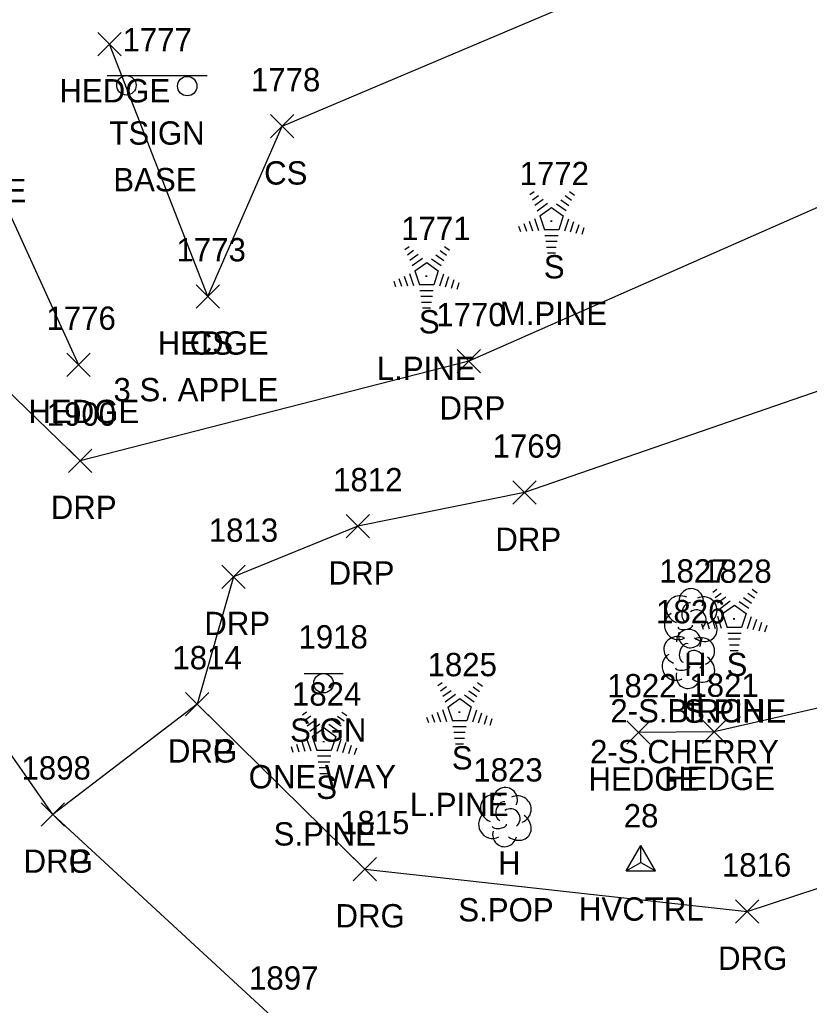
# Model space of a CAD drawing. Extents: x 1477930 to 1480780, y 774090 to 784647.
# Drawn here: x 1478985.1 to 1479052.8, y 774378.4 to 774462.9 of the extents above; entities that cross this region are included whole.
import ezdxf

# ---------------------------------------------------------------- set-up
doc = ezdxf.new("R2010")
doc.units = 0
for name, color, linetype in [('C_A', 7, 'Continuous'), ('C_I', 7, 'Continuous'), ('CPSM', 7, 'Continuous'), ('L_A', 7, 'Continuous'), ('L_C', 7, 'Continuous'), ('L_I', 7, 'Continuous'), ('L_TIC', 7, 'Continuous'), ('LAHR', 7, 'Continuous'), ('LELB', 7, 'Continuous'), ('LTC', 7, 'Continuous'), ('LTD', 7, 'Continuous'), ('R_A', 7, 'Continuous'), ('R_I', 7, 'Continuous'), ('R_TIC', 7, 'Continuous'), ('RDG', 7, 'Continuous'), ('RDP', 7, 'Continuous'), ('S_A', 7, 'Continuous'), ('S_C', 7, 'Continuous'), ('S_I', 7, 'Continuous'), ('SSGN', 7, 'Continuous')]:
    doc.layers.add(name, color=color, linetype=linetype)

msp = doc.modelspace()

# ---------------------------------------------------------------- linework, layer by layer
at = {"layer": 'CPSM'}
for p, q in [((1479037.081, 774389.906), (1479038.331, 774392.071)), ((1479039.581, 774389.906), (1479038.331, 774392.071)), ((1479038.332, 774390.627), (1479038.331, 774392.071)), ((1479037.081, 774389.906), (1479038.332, 774390.627)), ((1479038.332, 774390.627), (1479038.332, 774390.627)), ((1479038.332, 774390.627), (1479039.581, 774389.906)), ((1479037.081, 774389.906), (1479039.581, 774389.906))]:
    msp.add_line(p, q, dxfattribs=at)
at = {"layer": 'L_TIC'}
for points in [[(1478991.765, 774459.811), (1478993.765, 774461.811)], [(1478993.765, 774459.811), (1478991.765, 774461.811)], [(1479006.585, 774452.764), (1479008.585, 774454.764)], [(1479008.585, 774452.764), (1479006.585, 774454.764)], [(1479000.201, 774438.175), (1479002.201, 774440.175)], [(1479002.201, 774438.175), (1479000.201, 774440.175)], [(1479000.201, 774438.175), (1479002.201, 774440.175)], [(1479002.201, 774438.175), (1479000.201, 774440.175)], [(1478989.107, 774432.304), (1478991.107, 774434.304)], [(1478991.107, 774432.304), (1478989.107, 774434.304)], [(1479037.139, 774400.78), (1479039.139, 774402.78)], [(1479039.139, 774400.78), (1479037.139, 774402.78)], [(1479043.623, 774400.826), (1479045.623, 774402.826)], [(1479045.623, 774400.826), (1479043.623, 774402.826)]]:
    msp.add_lwpolyline(points, dxfattribs=at)
at = {"layer": 'LAHR'}
for points in [[(1479001.201, 774439.175), (1478992.765, 774460.811)], [(1478979.611, 774456.25), (1478990.107, 774433.304)], [(1479070.273, 774407.681), (1479044.623, 774401.826), (1479038.139, 774401.78)]]:
    msp.add_lwpolyline(points, dxfattribs=at)
at = {"layer": 'LELB'}
msp.add_lwpolyline([(1479001.201, 774439.175), (1479007.585, 774453.764), (1479050.28, 774471.874), (1479091.551, 774493.14), (1479101.547, 774520.781)], dxfattribs=at)
at = {"layer": 'LTC'}
for p, q in [((1479028.82, 774447.922), (1479029.175, 774448.18)), ((1479032.218, 774448.163), (1479032.638, 774447.858)), ((1479029.03, 774447.457), (1479029.559, 774447.841)), ((1479029.239, 774446.991), (1479029.943, 774447.502)), ((1479031.476, 774447.466), (1479032.155, 774446.972)), ((1479031.847, 774447.814), (1479032.397, 774447.415)), ((1479029.449, 774446.525), (1479030.327, 774447.163)), ((1479029.673, 774446.07), (1479030.685, 774446.805)), ((1479030.685, 774446.805), (1479031.682, 774446.08)), ((1479031.105, 774447.118), (1479031.915, 774446.529)), ((1479028.763, 774445.635), (1479029.035, 774444.799)), ((1479029.219, 774445.851), (1479029.55, 774444.832)), ((1479029.673, 774446.07), (1479030.06, 774444.877)), ((1479031.682, 774446.08), (1479031.291, 774444.877)), ((1479032.12, 774445.809), (1479031.782, 774444.769)), ((1479032.564, 774445.559), (1479032.277, 774444.674)), ((1479027.853, 774445.202), (1479028.005, 774444.734)), ((1479028.308, 774445.418), (1479028.52, 774444.767)), ((1479031.291, 774444.877), (1479030.06, 774444.877)), ((1479033.009, 774445.309), (1479032.772, 774444.579)), ((1479033.453, 774445.058), (1479033.266, 774444.484)), ((1479031.253, 774444.377), (1479030.108, 774444.377)), ((1479031.169, 774443.877), (1479030.18, 774443.877)), ((1479018.103, 774443.206), (1479018.457, 774443.464)), ((1479018.312, 774442.741), (1479018.842, 774443.125)), ((1479021.13, 774443.098), (1479021.68, 774442.699)), ((1479021.501, 774443.447), (1479021.92, 774443.142)), ((1479031.085, 774443.377), (1479030.253, 774443.377)), ((1479018.522, 774442.275), (1479019.226, 774442.786)), ((1479018.732, 774441.809), (1479019.61, 774442.447)), ((1479020.388, 774442.402), (1479021.197, 774441.813)), ((1479020.759, 774442.75), (1479021.438, 774442.256)), ((1479031.001, 774442.877), (1479030.326, 774442.877)), ((1479018.956, 774441.354), (1479019.968, 774442.089)), ((1479018.956, 774441.354), (1479019.343, 774440.161)), ((1479019.968, 774442.089), (1479020.965, 774441.364)), ((1479020.965, 774441.364), (1479020.574, 774440.161)), ((1479017.135, 774440.485), (1479017.287, 774440.017)), ((1479017.591, 774440.702), (1479017.802, 774440.05)), ((1479018.046, 774440.919), (1479018.317, 774440.083)), ((1479018.502, 774441.135), (1479018.832, 774440.116)), ((1479021.402, 774441.093), (1479021.065, 774440.053)), ((1479021.847, 774440.842), (1479021.56, 774439.958)), ((1479022.292, 774440.592), (1479022.055, 774439.863)), ((1479020.574, 774440.161), (1479019.343, 774440.161)), ((1479020.535, 774439.661), (1479019.391, 774439.661)), ((1479022.736, 774440.342), (1479022.549, 774439.768)), ((1479020.452, 774439.161), (1479019.463, 774439.161)), ((1479020.368, 774438.661), (1479019.536, 774438.661)), ((1479020.284, 774438.161), (1479019.609, 774438.161)), ((1479044.495, 774413.813), (1479044.85, 774414.07)), ((1479044.705, 774413.348), (1479045.234, 774413.732)), ((1479047.522, 774413.705), (1479048.072, 774413.306)), ((1479047.893, 774414.053), (1479048.312, 774413.749)), ((1479044.914, 774412.882), (1479045.618, 774413.393)), ((1479045.124, 774412.416), (1479046.002, 774413.054)), ((1479045.348, 774411.961), (1479046.36, 774412.695)), ((1479046.36, 774412.695), (1479047.357, 774411.97)), ((1479046.78, 774413.008), (1479047.59, 774412.42)), ((1479047.151, 774413.357), (1479047.83, 774412.863)), ((1479044.894, 774411.742), (1479045.225, 774410.723)), ((1479045.348, 774411.961), (1479045.735, 774410.768)), ((1479047.357, 774411.97), (1479046.966, 774410.768)), ((1479043.527, 774411.092), (1479043.68, 774410.624)), ((1479043.983, 774411.309), (1479044.195, 774410.657)), ((1479044.438, 774411.525), (1479044.71, 774410.69)), ((1479047.795, 774411.7), (1479047.457, 774410.66)), ((1479048.239, 774411.449), (1479047.952, 774410.565)), ((1479048.684, 774411.199), (1479048.447, 774410.47)), ((1479049.128, 774410.949), (1479048.941, 774410.375)), ((1479046.966, 774410.768), (1479045.735, 774410.768)), ((1479046.927, 774410.268), (1479045.783, 774410.268)), ((1479046.844, 774409.768), (1479045.855, 774409.768)), ((1479046.76, 774409.268), (1479045.928, 774409.268)), ((1479046.676, 774408.768), (1479046.001, 774408.768)), ((1479020.931, 774405.802), (1479021.286, 774406.059)), ((1479024.329, 774406.042), (1479024.749, 774405.738)), ((1479021.141, 774405.337), (1479021.67, 774405.721)), ((1479021.35, 774404.871), (1479022.054, 774405.382)), ((1479021.56, 774404.405), (1479022.438, 774405.043)), ((1479023.216, 774404.997), (1479024.026, 774404.409)), ((1479023.587, 774405.346), (1479024.266, 774404.852)), ((1479023.958, 774405.694), (1479024.508, 774405.295)), ((1479021.784, 774403.95), (1479022.796, 774404.684)), ((1479022.796, 774404.684), (1479023.793, 774403.959)), ((1479009.302, 774403.279), (1479009.656, 774403.537)), ((1479012.7, 774403.52), (1479013.119, 774403.215)), ((1479020.419, 774403.298), (1479020.631, 774402.646)), ((1479020.874, 774403.514), (1479021.146, 774402.679)), ((1479021.33, 774403.731), (1479021.661, 774402.712)), ((1479021.784, 774403.95), (1479022.171, 774402.757)), ((1479023.793, 774403.959), (1479023.402, 774402.757)), ((1479024.231, 774403.689), (1479023.893, 774402.649)), ((1479024.675, 774403.438), (1479024.388, 774402.554)), ((1479009.511, 774402.814), (1479010.041, 774403.198)), ((1479009.721, 774402.348), (1479010.425, 774402.859)), ((1479009.931, 774401.882), (1479010.809, 774402.52)), ((1479011.587, 774402.475), (1479012.396, 774401.886)), ((1479011.958, 774402.823), (1479012.637, 774402.329)), ((1479012.329, 774403.171), (1479012.878, 774402.772)), ((1479019.964, 774403.081), (1479020.116, 774402.613)), ((1479023.402, 774402.757), (1479022.171, 774402.757)), ((1479025.12, 774403.188), (1479024.883, 774402.459)), ((1479025.564, 774402.938), (1479025.377, 774402.364)), ((1479010.155, 774401.427), (1479011.167, 774402.162)), ((1479011.167, 774402.162), (1479012.164, 774401.437)), ((1479023.364, 774402.257), (1479022.219, 774402.257)), ((1479023.28, 774401.757), (1479022.291, 774401.757)), ((1479008.79, 774400.775), (1479009.001, 774400.123)), ((1479009.245, 774400.992), (1479009.516, 774400.156)), ((1479009.701, 774401.208), (1479010.031, 774400.189)), ((1479010.155, 774401.427), (1479010.542, 774400.234)), ((1479012.164, 774401.437), (1479011.773, 774400.234)), ((1479012.601, 774401.166), (1479012.263, 774400.126)), ((1479013.046, 774400.915), (1479012.758, 774400.031)), ((1479023.196, 774401.257), (1479022.364, 774401.257)), ((1479023.112, 774400.757), (1479022.437, 774400.757)), ((1479008.334, 774400.558), (1479008.486, 774400.09)), ((1479011.773, 774400.234), (1479010.542, 774400.234)), ((1479013.491, 774400.665), (1479013.253, 774399.936)), ((1479013.935, 774400.415), (1479013.748, 774399.841)), ((1479011.734, 774399.734), (1479010.59, 774399.734)), ((1479011.651, 774399.234), (1479010.662, 774399.234)), ((1479011.567, 774398.734), (1479010.735, 774398.734)), ((1479011.483, 774398.234), (1479010.808, 774398.234))]:
    msp.add_line(p, q, dxfattribs=at)
at = {"layer": 'LTD'}
for p, q in [((1479042.603, 774411.627), (1479042.603, 774411.627)), ((1479042.603, 774411.627), (1479042.603, 774411.627)), ((1479042.39, 774408.133), (1479042.39, 774408.133)), ((1479042.39, 774408.133), (1479042.39, 774408.133)), ((1479026.657, 774394.562), (1479026.657, 774394.562)), ((1479026.657, 774394.562), (1479026.657, 774394.562))]:
    msp.add_line(p, q, dxfattribs=at)
for centre in [(1479042.65, 774413.061), (1479042.436, 774409.567), (1479026.704, 774395.996)]:
    msp.add_arc(centre, 1.047, 335.52715, 180.95627, dxfattribs=at)
for centre, major_axis, ratio, start_param, end_param in [((1479041.811, 774412.294), (1.21, -0.512), 0.895232, 1.570796, 4.712389), ((1479043.644, 774412.211), (-1.141, -0.483), 0.949671, 1.570796, 4.712389), ((1479042.394, 774412.086), (-0.208, -0.792), 0.645439, 3.141593, 6.283185), ((1479041.52, 774410.919), (0.584, -1.042), 0.959034, 3.141593, 6.283185), ((1479043.103, 774411.461), (-0.5, 0.667), 0.989748, 3.141593, 6.283185), ((1479042.145, 774410.877), (-0.625, -0.083), 0.423636, 0, 3.141593), ((1479043.603, 774410.794), (-1.09, 0.792), 0.841452, 1.570796, 4.712389), ((1479041.598, 774408.799), (1.21, -0.512), 0.895232, 1.570796, 4.712389), ((1479042.603, 774410.127), (0.265, 1.061), 0.942809, 1.570796, 4.712389), ((1479043.431, 774408.716), (-1.141, -0.483), 0.949671, 1.570796, 4.712389), ((1479042.181, 774408.591), (-0.208, -0.792), 0.645439, 3.141593, 6.283185), ((1479041.306, 774407.424), (0.584, -1.042), 0.959034, 3.141593, 6.283185), ((1479042.89, 774407.966), (-0.5, 0.667), 0.989748, 3.141593, 6.283185), ((1479043.39, 774407.3), (-1.09, 0.792), 0.841452, 1.570796, 4.712389), ((1479042.39, 774406.633), (0.265, 1.061), 0.942809, 1.570796, 4.712389), ((1479041.931, 774407.383), (-0.625, -0.083), 0.423636, 0, 3.141593), ((1479025.865, 774395.229), (1.21, -0.512), 0.895232, 1.570796, 4.712389), ((1479026.448, 774395.02), (-0.208, -0.792), 0.645439, 3.141593, 6.283185), ((1479027.698, 774395.146), (-1.141, -0.483), 0.949671, 1.570796, 4.712389), ((1479025.574, 774393.854), (0.584, -1.042), 0.959034, 3.141593, 6.283185), ((1479027.157, 774394.396), (-0.5, 0.667), 0.989748, 3.141593, 6.283185), ((1479027.657, 774393.729), (-1.09, 0.792), 0.841452, 1.570796, 4.712389), ((1479026.657, 774393.062), (0.265, 1.061), 0.942809, 1.570796, 4.712389), ((1479026.199, 774393.812), (-0.625, -0.083), 0.423636, 0, 3.141593)]:
    msp.add_ellipse(centre, major_axis=major_axis, ratio=ratio, start_param=start_param, end_param=end_param, dxfattribs=at)
at = {"layer": 'R_TIC'}
for points in [[(1479022.572, 774432.612), (1479024.572, 774434.612)], [(1479024.572, 774432.612), (1479022.572, 774434.612)], [(1478989.24, 774424.08), (1478991.24, 774426.08)], [(1478991.24, 774424.08), (1478989.24, 774426.08)], [(1479027.367, 774421.341), (1479029.367, 774423.341)], [(1479029.367, 774421.341), (1479027.367, 774423.341)], [(1479013.067, 774418.453), (1479015.067, 774420.453)], [(1479015.067, 774418.453), (1479013.067, 774420.453)], [(1479002.406, 774414.123), (1479004.406, 774416.123)], [(1479004.406, 774414.123), (1479002.406, 774416.123)], [(1478999.285, 774403.185), (1479001.285, 774405.185)], [(1479001.285, 774403.185), (1478999.285, 774405.185)], [(1478999.285, 774403.185), (1479001.285, 774405.185)], [(1479001.285, 774403.185), (1478999.285, 774405.185)], [(1478986.908, 774393.732), (1478988.908, 774395.732)], [(1478988.908, 774393.732), (1478986.908, 774395.732)], [(1478986.908, 774393.732), (1478988.908, 774395.732)], [(1478988.908, 774393.732), (1478986.908, 774395.732)], [(1479013.659, 774389.047), (1479015.659, 774391.047)], [(1479015.659, 774389.047), (1479013.659, 774391.047)], [(1479046.464, 774385.408), (1479048.464, 774387.408)], [(1479048.464, 774385.408), (1479046.464, 774387.408)]]:
    msp.add_lwpolyline(points, dxfattribs=at)
at = {"layer": 'RDG'}
msp.add_lwpolyline([(1479000.285, 774404.185), (1479014.659, 774390.047), (1479047.464, 774386.408), (1479082.424, 774397.913), (1479092.78, 774404.139), (1479080.31, 774426.656), (1479099.491, 774435.861), (1479111.25, 774415.085), (1479119.414, 774407.602), (1479089.107, 774388.499), (1479108.735, 774376.691), (1479096.509, 774359.631), (1479079.071, 774370.658), (1479068.454, 774377.31), (1479035.786, 774371.215), (1479007.425, 774376.712), (1478987.908, 774394.732)], dxfattribs=at)
at = {"layer": 'RDP'}
for points in [[(1479196.157, 774549.722), (1479150.608, 774530.18), (1479100.702, 774505.669), (1479114.057, 774476.034), (1479101.265, 774468.925), (1479068.733, 774453.512), (1479023.572, 774433.612), (1478990.24, 774425.08), (1478973.522, 774441.237), (1478963.537, 774465.835), (1478965.909, 774472.744)], [(1479362.085, 774490.122), (1479342.053, 774496.544), (1479325.922, 774501.653), (1479312.309, 774505.809), (1479281.235, 774507.912), (1479260.189, 774507.512), (1479228.518, 774504.276), (1479173.381, 774482.974), (1479136.115, 774464.126), (1479110.894, 774453.252), (1479073.731, 774438.018), (1479028.367, 774422.341), (1479014.067, 774419.453), (1479003.406, 774415.123), (1479000.285, 774404.185), (1478987.908, 774394.732), (1478976.965, 774410.388), (1478964.404, 774425.192), (1478951.82, 774441.875), (1478940.933, 774454.02), (1478935.821, 774456.705)]]:
    msp.add_lwpolyline(points, dxfattribs=at)
at = {"layer": 'SSGN'}
for p, q in [((1478992.557, 774458.11), (1479001.154, 774458.11)), ((1478996.579, 774457.206), (1478996.579, 774457.206)), ((1479009.47, 774406.826), (1479012.803, 774406.826)), ((1479011.116, 774405.992), (1479011.116, 774405.992))]:
    msp.add_line(p, q, dxfattribs=at)
for centre in [(1478994.218, 774457.276), (1478999.433, 774457.206), (1479011.116, 774405.992)]:
    msp.add_circle(centre, 0.833, dxfattribs=at)

# ---------------------------------------------------------------- texts
at = {"layer": 'C_A'}
msp.add_text('HVCTRL', height=2, dxfattribs=at).set_placement((1479033.024, 774385.627))
at = {"layer": 'C_I'}
msp.add_text('28', height=2, dxfattribs=at).set_placement((1479036.867, 774393.627))
at = {"layer": 'L_A'}
for s, p in [('HEDGE', (1478988.466, 774455.811)), ('CS', (1479006.025, 774448.764)), ('S', (1479030.011, 774440.714)), ('S', (1479019.294, 774435.998)), ('HEDGE', (1478996.902, 774434.175)), ('CS', (1478999.642, 774434.175)), ('HEDGE', (1478985.808, 774428.304)), ('H', (1479042.036, 774406.627)), ('S', (1479045.686, 774406.605)), ('H', (1479041.823, 774403.133)), ('S', (1479022.122, 774398.594)), ('HEDGE', (1479033.84, 774396.78)), ('HEDGE', (1479040.323, 774396.826)), ('S', (1479010.492, 774396.071)), ('H', (1479026.09, 774389.562))]:
    msp.add_text(s, height=2, dxfattribs=at).set_placement(p)
at = {"layer": 'L_C'}
for s, p in [('4 S. APPLE', (1478971.517, 774447.25)), ('M.PINE', (1479026.231, 774436.714)), ('L.PINE', (1479015.687, 774431.998)), ('3 S. APPLE', (1478993.107, 774430.175)), ('2-S.BIRCH', (1479035.721, 774402.627)), ('S.PINE', (1479042.032, 774402.605)), ('2-S.CHERRY', (1479033.98, 774399.133)), ('L.PINE', (1479018.515, 774394.594)), ('S.PINE', (1479006.839, 774392.071)), ('S.POP', (1479022.68, 774385.562))]:
    msp.add_text(s, height=2, dxfattribs=at).set_placement(p)
at = {"layer": 'L_I'}
for s, p in [('1778', (1479004.892, 774456.764)), ('1772', (1479027.932, 774448.714)), ('1771', (1479017.782, 774443.998)), ('1773', (1478998.509, 774442.175)), ('1773', (1478998.509, 774442.175)), ('1776', (1478987.359, 774436.304)), ('1827', (1479039.91, 774414.627)), ('1828', (1479043.607, 774414.605)), ('1826', (1479039.641, 774411.133)), ('1825', (1479020.043, 774406.594)), ('1822', (1479035.446, 774404.78)), ('1821', (1479042.497, 774404.826)), ('1824', (1479008.414, 774404.071)), ('1823', (1479023.964, 774397.562))]:
    msp.add_text(s, height=2, dxfattribs=at).set_placement(p)
at = {"layer": 'LTC'}
for p in [(1479030.568, 774445.818), (1479019.85, 774441.102), (1479046.242, 774411.709), (1479022.679, 774403.698), (1479011.049, 774401.175)]:
    msp.add_text('.', height=1.037, rotation=270, dxfattribs=at).set_placement(p)
at = {"layer": 'R_A'}
for s, p in [('DRP', (1479021.06, 774428.612)), ('DRP', (1478987.728, 774420.08)), ('DRP', (1479025.855, 774417.341)), ('DRP', (1479011.555, 774414.453)), ('DRP', (1479000.894, 774410.123)), ('DRG', (1478997.773, 774399.185)), ('DRP', (1478997.773, 774399.185)), ('DRG', (1478985.397, 774389.732)), ('DRP', (1478985.397, 774389.732)), ('DRG', (1479012.147, 774385.047)), ('DRG', (1479044.952, 774381.408))]:
    msp.add_text(s, height=2, dxfattribs=at).set_placement(p)
at = {"layer": 'R_I'}
for s, p in [('1770', (1479020.793, 774436.612)), ('1900', (1478987.382, 774428.08)), ('1769', (1479025.619, 774425.341)), ('1812', (1479011.941, 774422.453)), ('1813', (1479001.28, 774418.123)), ('1814', (1478998.159, 774407.185)), ('1814', (1478998.159, 774407.185)), ('1898', (1478985.215, 774397.732)), ('1898', (1478985.215, 774397.732)), ('1815', (1479012.533, 774393.047)), ('1816', (1479045.283, 774389.408)), ('1897', (1479004.733, 774379.712))]:
    msp.add_text(s, height=2, dxfattribs=at).set_placement(p)
at = {"layer": 'S_A'}
for s, p in [('TSIGN', (1478992.755, 774452.188)), ('SIGN', (1479008.254, 774400.972))]:
    msp.add_text(s, height=2, dxfattribs=at).set_placement(p)
at = {"layer": 'S_C'}
for s, p in [('BASE', (1478993.093, 774448.188)), ('ONE WAY', (1479004.703, 774396.972))]:
    msp.add_text(s, height=2, dxfattribs=at).set_placement(p)
at = {"layer": 'S_I'}
for s, p in [('1777', (1478993.881, 774460.188)), ('1918', (1479008.971, 774408.972))]:
    msp.add_text(s, height=2, dxfattribs=at).set_placement(p)

doc.saveas('drawing.dxf')
